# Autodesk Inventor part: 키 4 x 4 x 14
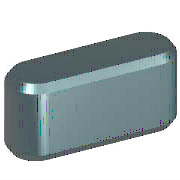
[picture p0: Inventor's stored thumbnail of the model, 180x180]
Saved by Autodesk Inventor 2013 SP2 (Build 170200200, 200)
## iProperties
IsCustomPart: 1
Created: 2012-02
Part Number: 키 4 x 4 x 14
Material: 강철, 연강
Description: 키 및 해당 키홈
Document SubType Name: Modeling
Standard: KS B 1311
Designer: mduedu
Standards Organization: KS
Language: ko-KR
Size Designation: 4 x 4 x 12
Categories: <MemberInstance><Categories><Category DisplayName="샤프트 부품" InternalName="7f7aeb1f-a693-4053-b835-cee3144e0d98" Mnemonic="SHFT"><Category DisplayName="키" Interna
Density: 1 g/cm^3
Author: mduedu
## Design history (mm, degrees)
workplane "Work Plane1"
workplane "Work Plane2"
sketch "스케치1"
  geometry: L1 (2, 2)-(12, 2); L2 (12, -2)-(2, -2); L3 (0, 8.8)-(0, -3.8) reference; L4 (-2.4, 0)-(14.4, 0) reference; L5 (14, 0)-(14, 7); A1 r 2 centre (2, 0) between (2, 2) and (2, -2); A2 r 2 centre (12, 0) between (12, -2) and (12, 2)
  constraints: 6 end point, 5 point on circle, 4 tangent, 3 point on line, 2 centre point, 1 horizontal, 1 parallel, 1 perpendicular
  dimensions: "d0" = 2 radius of A1 (= 0.5 x PB); "d13" = 2 radius of A2 (= 0.5 x PB); "d14" = 14 distance between parallel lines of L5 L3 (= NLG)
extrude "본체1" new body sketch "스케치1" taper "d3" = 0 deg; stored distance "d4" = 10
workplane "Work Plane3"
body "Solid1"
chamfer "모따기1" distance "d8" = 0.25 (= PHH); stored, may be unused: second distance "d9" = 0.25 (= PHH), angle "d15" = 45 deg
other parameters: "d1" = -2.5 (= -PNT), "d2" = 1.5 (= PH - PNT), "NLG" = 14 [user parameter; used in 3 equation terms], "PB" = 4 [user parameter; used in 2 equation terms], "PNT" = 2.5 [user parameter; used in 2 equation terms], "PH" = 4 [user parameter; used in 1 equation term], "PHH" = 0.25 [user parameter; used in 2 equation terms], "d10" = 0, "d16" = 0, "d17" = 0, "d18" = 0, "PLB2" = 14 (= NLG) [user parameter], "WDMAX" = 12 [user parameter], "PLB1" = 14 (= NLG) [user parameter], "RR" = 0.08 [user parameter], "PUEB" = 1.8 [user parameter]
